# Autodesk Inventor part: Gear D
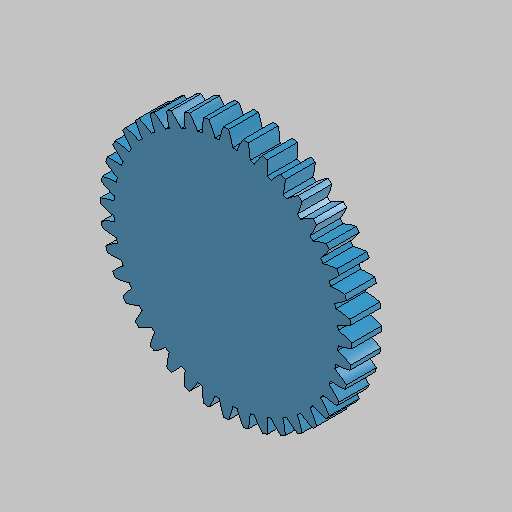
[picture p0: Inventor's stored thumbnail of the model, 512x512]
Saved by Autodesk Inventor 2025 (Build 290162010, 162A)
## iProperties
Created: 2024-10
Part Number: Gear D
Material: Generic
Document SubType Name: Modeling
Designer: Dennis
Density: 1 g/cm^3
Appearance: Sky Blue Dark
Mass: 50.4473 g
Surface Area: 152.927 cm^2
Volume: 50.4473 cm^3
Author: Dennis
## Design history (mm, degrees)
sketch "Sketch1"
  geometry: L1 (0, 0)-(42, 0); L2 (42, 0)-(42, -10); L3 (42, -10)-(5, -10); L4 (5, -10)-(5, -15); L5 (5, -15)-(2.5, -15); L6 (2.5, -15)-(2.5, -20); L7 (2.5, -20)-(0, -20); L8 (0, -20)-(0, 0)
  constraints: 16 end point, 7 perpendicular, 1 horizontal
  dimensions: "d0" = 10 distance of L1.end L2.end; "d1" = 5 distance of L3.end L4.end; "d2" = 5 distance of L5.end L6.end; "d3" = 5 diameter of L6 L8; "d4" = 10 diameter of L4 L8; "d5" = 84 diameter of L2 L8
revolve "Revolution1" sketch "Sketch1" stored, may be unused: angle "d6" = 90 deg
sketch "Sketch2"
  geometry: C1 r 40 at (0, 0); 1 further point
  constraints: 1 centre point, 1 coincident
  dimensions: "d7" = 80 diameter of C1
extrude_surface "ExtrusionSrf1" sketch "Sketch2" dims "d8" = 10, "d9" = 0
node "Spur Gear Teeth1"
body "Solid1"
body "Srf1"
feature "Spur Gear2"
